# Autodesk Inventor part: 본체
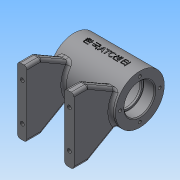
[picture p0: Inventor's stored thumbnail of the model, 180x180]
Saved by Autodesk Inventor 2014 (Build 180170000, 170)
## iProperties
Created: 2018-05
Part Number: 본체
Material: 일반
Document SubType Name: Modeling
Designer: NET
Density: 1 g/cm^3
Appearance: 기본값
Author: NET
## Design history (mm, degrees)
sketch "스케치1"
  geometry: L1 (-35, 0)-(35, 0) reference; L2 (35, 0)-(35, 26); L3 (35, 26)-(-35, 26); L4 (-35, 26)-(-35, 0); L5 (35, 16)-(23, 16); L6 (23, 16)-(23, 14); L7 (23, 14)-(21, 14); L8 (21, 14)-(21, 21); L9 (21, 21)-(-21, 21); L10 (-21, 21)-(-21, 14); L11 (-21, 14)-(-23, 14); L12 (-23, 14)-(-23, 16); L13 (-23, 16)-(-35, 16); 1 further point
  constraints: 26 end point, 7 parallel, 4 equal length, 4 perpendicular, 2 horizontal, 2 point on line, 1 collinear
  dimensions: "d0" = 70 distance of L1.start L1.end; "d1" = 35 distance of L1.end point (0, 0); "d2" = 26 distance of L1.end L2.end; "d3" = 42 distance of L8.end L9.end; "d4" = 28 diameter of L7 L1; "d5" = 12 distance of L5.start L5.end; "d6" = 32 diameter of L5 L1; "d7" = 42 diameter of L9 L1
revolve "회전1" sketch "스케치1" stored, may be unused: angle "d8" = 90 deg
node "작업 평면1"
sketch "스케치2"
  geometry: L1 (-30, 35)-(-20, 35); L2 (-20, 35)-(-20, -35); L3 (-20, -35)-(-30, -35); L4 (-30, -35)-(-30, 35); L5 (20, 35)-(30, 35); L6 (30, 35)-(30, -35); L7 (30, -35)-(20, -35); L8 (20, -35)-(20, 35); 1 further point
  constraints: 16 end point, 4 parallel, 2 equal length, 2 horizontal, 2 horizontal alignment, 2 perpendicular
  dimensions: "d10" = 70 distance of L3.end L1.start; "d11" = 40 distance between parallel lines of L8 L2; "d12" = 20 distance from line of L8 point (0, 0); "d13" = 10 distance of L1.start L1.end; "d14" = 35 distance from line of L1 point (0, 0)
extrude "돌출1" join sketch "스케치2" distance "d15" = 15; taper "d16" = 0 deg
sketch "스케치3"
  geometry: L1 (70, 0)-(70, 15) reference; L2 (0, 15)-(70, 15) reference; L3 (0, 0)-(0, 15) reference; L4 (0, 15)-(17.675, 45.614); L5 (52.325, 45.614)-(70, 15); A1 r 26 centre (35, 65) between (17.675, 45.614) and (52.325, 45.614); 1 further point
  constraints: 4 end point, 2 point on circle, 1 centre point, 1 coincident
  dimensions: "d17" = 30 deg angle of L3 L4; "d18" = 30 deg angle of L1 L5; "d19" = 52 diameter of A1
extrude "돌출2" join sketch "스케치3" distance "d20" = 10; taper "d21" = 0 deg
sketch "스케치4"
  geometry: L1 (70, 0)-(70, 15) reference; L2 (0, 15)-(70, 15) reference; L3 (0, 0)-(0, 15) reference; L4 (70, 15)-(52.325, 45.614); L5 (0, 15)-(17.675, 45.614); A1 r 26 centre (35, 65) between (17.675, 45.614) and (52.325, 45.614); 1 further point
  constraints: 4 end point, 2 point on circle, 1 centre point, 1 coincident
  dimensions: "d22" = 30 deg angle of L3 L5; "d23" = 30 deg angle of L1 L4; "d24" = 52 diameter of A1
extrude "돌출3" join sketch "스케치4" distance "d25" = 10; taper "d26" = 0 deg
sketch "스케치5"
  geometry: L1 (0, 0)-(-27.251, -9.919); L2 (0, 0)-(-29, 0); L3 (-27.251, -9.919)-(-25.199, -15.557); L4 (-25.199, -15.557)-(-18.621, -13.163); L5 (-18.621, -13.163)-(-20.673, -7.524)
  constraints: 10 end point, 3 perpendicular, 1 horizontal, 1 point on line
  dimensions: "d27" = 29 distance of L1.start L1.end; "d28" = 29 distance of L1.start L2.end; "d29" = 20 deg angle of L1 L2; "d30" = 6 distance of L1.end L3.end; "d31" = 7 distance of L3.end L4.end
revolve "회전2" sketch "스케치5" stored, may be unused: angle "d32" = 90 deg
node "작업 평면2"
sketch "스케치6"
  geometry: C1 r 5 at (0, 0); 1 further point
  constraints: 1 centre point, 1 coincident
  dimensions: "d34" = 10 diameter of C1
extrude "돌출4" join sketch "스케치6" stored distance "d35" = 10; taper "d36" = 0 deg
sketch "스케치7"
  geometry: C1 r 26 at (0, 0) reference; 4 further points
  constraints: 1 vertical alignment, 5 other
  dimensions: "d37" = 21 distance of C1.centre point (0, 21); "d40" = 360 deg dimension on C1.centre point (0, 21) (derived)
hole "구멍1" sketch "스케치7" at (0, 21), (-21, 0), (0, -21), (21, 0) diameter "d42" = 3.242; stored, may be unused: countersink angle "d46" = 90 deg, drill point angle "d48" = 118 deg; dims "d43" = 8, "d44" = 4, "d45" = 2, "d47" = 10
sketch "스케치8"
  geometry: C1 r 5 at (0, 0) reference; 1 further point
  constraints: 1 coincident
hole "구멍2" sketch "스케치8" at (0, 0) diameter "d49" = 5.188; stored, may be unused: countersink angle "d53" = 90 deg, drill point angle "d55" = 118 deg; dims "d50" = 8, "d51" = 4, "d52" = 2, "d54" = 20
sketch "스케치9"
  geometry: C1 r 6 at (0, 0) reference; 1 further point
  constraints: 1 coincident
hole "구멍3" sketch "스케치9" at (0, 0) diameter "d56" = 5.188; stored, may be unused: countersink angle "d60" = 90 deg, drill point angle "d62" = 118 deg; dims "d57" = 8, "d58" = 4, "d59" = 2, "d61" = 20
sketch "스케치10"
  geometry: L1 (30, -35)-(30, 35) reference; L2 (-20, -35)-(-20, 35) reference; 5 further points
  constraints: 2 horizontal alignment, 2 vertical alignment
  dimensions: "d63" = 5 distance from line of L1 point (25, 20); "d64" = 20 vertical distance of point (0, 0) point (25, 20); "d65" = 40 distance of point (25, -20) point (25, 20); "d66" = 5 distance from line of point (-25, 20) L2
hole "구멍4" sketch "스케치10" at (25, 20), (25, -20), (-25, 20), (-25, -20) diameter "d67" = 4.134; stored, may be unused: countersink angle "d71" = 90 deg, drill point angle "d73" = 118 deg; dims "d68" = 8, "d69" = 4, "d70" = 2, "d72" = 10
node "작업 평면3"
sketch "스케치11"
  geometry: L1 (-35, -26)-(-35, 26) reference; 2 further points
  constraints: 1 other
  dimensions: "d75" = 35 distance from line of point (0, 0) L1; "d76" = 26 vertical distance of L1.end point (0, 0)
feature "엠보싱1" sketch "스케치11" dims "d10" = 70, "d11" = 40, "d12" = 20, "d13" = 10, "d14" = 35, "d77" = 0.5, "d78" = 0
fillet "모깎기1" dims "d79" = 2, "d80" = 0.3, "d81" = 3
chamfer "모따기1" distance "d82" = 1; stored, may be unused: second distance "d83" = 2, angle "d84" = 45 deg
node "솔리드1"
mirror "대칭1"
other parameters: "d9" = -65, "d33" = 29, "d74" = 26
